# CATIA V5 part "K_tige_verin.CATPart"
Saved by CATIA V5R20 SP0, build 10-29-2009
Part number: tige_verin
Publications: "Corps principal", "tige_verin", "Plan_bout_tige", "Point.1", "Plan.4"
Bounding box of the stored display mesh (mm): x -25 to 25, y -398.957 to -151.18, z 183.79 to 486.128
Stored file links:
  G:\Khaled_CFAO_2011\ST2M\ST2M_GR2\echouteau\Khaled\CAD_ThinkMotion\K_tige_verin.CATPart
  F:\2A\Proj Think Motion\trainv3\Version3\sql_general.CATProduct
  G:\Khaled_CFAO_2011\ST2M\ST2M_GR2\echouteau\echouteau\bogie_beam.CATPart
  G:\Khaled_CFAO_2011\ST2M\ST2M_GR2\echouteau\echouteau\tige.CATPart
  G:\Khaled_CFAO_2011\ST2M\ST2M_GR2\echouteau\Khaled\CAD_ThinkMotion\K_corps.CATPart
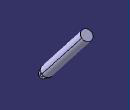
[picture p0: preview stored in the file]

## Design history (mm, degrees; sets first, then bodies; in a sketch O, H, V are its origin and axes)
Parameters
  Longueur_tige_verin = 300 mm
Set1
  Line1: linked copy from another document
  Point1: linked copy from another document
  Point2: linked copy from another document
Body1 (main body)
  Point3: type OnCurve, Support Line1, Length 0
  Line2 "direction_verin": type PtPt, FirstPoint Point3, SecondPoint Point1
  Point4 "Point_longueur_tige_verin": type OnCurve, Support Line2, Length 345 {= Longueur_tige_verin*1.15}
  Line3 "tige_verin": type PtPt, FirstPoint Point3, SecondPoint Point4
  Plane1 "Plan_pivot_bogie_tige_verin": type Normal, Curve Line3, RefPoint Point3
  Plane2 "Plan_bout_tige": type OffsetPt, RefPlane Plane1, RefPoint Point4
  Plane3: type 1Line1Pt, RefPoint Point2, Line Line2
  Plane4: type OffsetPt, RefPlane Plane3, RefPoint Point4
  Line4: type PtDir, RefPoint Point3, Direction yz-plane, Start -189, End 0
  Plane5: type OffsetPt, RefPlane yz-plane, RefPoint vertex of Line4
  Plane6: type Offset, RefPlane Plane1, Offset 20
  Sketch1 on Plane6, origin (0, -36.8776, -47.0748), H (-1, 0, 0), V (0, -0.7872, 0.6167)
    circle A1 centre (0, 424.7786) radius 25
    point P1 (0, 424.7786)
    reference projected point E1 (0, 424.7786) from Point3
    coincidence: P1 E1
  Pad1: profile Sketch1, direction (0, 0.6167, 0.7872), up to Plane2
  Line5 "direction_verin": stored without definition
  Sketch2 on Plane6, origin (0, -36.8776, -47.0748), H (-1, 0, 0), V (0, -0.7872, 0.6167)
    line L1 (0, 444.7786) -> (14, 444.7786)
    point P1 (0, 444.7786)
    point P2 (14, 444.7786)
    reference projected point E1 (0, 424.7786) from Point3
    line L2 (14, 444.7786) -> (14, 404.7786)
    point P3 (14, 404.7786)
    line L3 (14, 404.7786) -> (0, 404.7786)
    point P4 (0, 404.7786)
    point P5 (-14, 444.7786)
    point P6 (0, 444.7786)
    line L4 (0, 444.7786) -> (-14, 444.7786)
    point P7 (-14, 404.7786)
    line L5 (-14, 444.7786) -> (-14, 404.7786)
    point P8 (0, 404.7786)
    line L6 (-14, 404.7786) -> (0, 404.7786)
    distance E1 P1 = 20
    length L2 = 40
    length L1 = 14
    coincidence: P1 V, P4 V, P1 P6, P4 P8
    horizontal: L1 H, L3 H
    vertical: L2 V
    symmetry: P2 P5 V, P1 P6 V, L1 L4 V, P3 P7 V, L2 L5 V, P4 P8 V, L3 L6 V
  Sketch3 on yz-plane, origin (0, 0, 0), H (0, 1, 0), V (0, 0, 1)
    arc A1 centre (-383.6009, 199.136) radius 15.3563 from (-397.7763, 205.0416) to (-374.4736, 186.7867) ccw
    point P1 (-383.6009, 199.136)
    reference projected point E1 (-383.6009, 199.136) from Point3
    point P2 (-371.0472, 215.1611)
    point P3 (-355.571, 202.4853)
    reference projected line E2 (-383.6009, 199.136) -> (-50.077, 624.8845) from Line5
    line L1 (-374.4736, 186.7867) -> (-355.571, 202.4853)
    point P4 (-374.4736, 186.7867)
    reference projected line E3 (-383.6009, 199.136) -> (-50.077, 624.8845) from Line2
    point P7 (-387.0594, 227.1528)
    point P8 (-397.7763, 205.0416)
    line L2 (-397.7763, 205.0416) -> (-387.0594, 227.1528)
    line L3 (-355.571, 202.4853) -> (-387.0594, 227.1528)
    length L3 = 40
    coincidence: P1 E1, P2 E2
    symmetry: P3 P7 E3, P4 P8 E3, L1 L2 E3
    perpendicularity: L3 E3
  SolidCombine1: FirstComponentProfile Sketch2, FirstComponentDirection Sketch2, SecondComponentProfile Sketch3, SecondComponentDirection Sketch3
  Sketch4 on face of SolidCombine1 from Sketch2.L5, origin (14, -387.7579, 215.3361), H (0, 1, 0), V (0, 0, 1)
    point P1 (4.1569, -16.2)
    reference projected arc E1 centre (4.1569, -16.2) radius 15.3563 from (-10.0184, -10.2945) to (13.2842, -28.5494) ccw from edge [face of SolidCombine1 from Sketch3.A1 | face of SolidCombine1 from Sketch2.L5]
    concentricity: P1 E1
  Hole1: placed by Sketch4, at (14, -383.6009, 199.136) direction (-1, 0, 0), diameter 15, up to face of SolidCombine1 from Sketch2.L2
